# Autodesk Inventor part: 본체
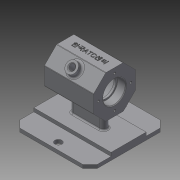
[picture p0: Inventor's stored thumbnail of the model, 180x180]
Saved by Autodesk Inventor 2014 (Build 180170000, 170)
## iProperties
Created: 2018-06
Part Number: 본체
Material: Generic
Document SubType Name: Modeling
Designer: geosung1
Density: 1 g/cm^3
Appearance: Default
Author: geosung1
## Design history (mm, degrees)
sketch "스케치1" dims "d0" = 60
  geometry: L1 (12.426, 30)-(30, 12.426); L2 (30, 12.426)-(30, -12.426); L3 (30, -12.426)-(12.426, -30); L4 (12.426, -30)-(-12.426, -30); L5 (-12.426, -30)-(-30, -12.426); L6 (-30, -12.426)-(-30, 12.426); L7 (-30, 12.426)-(-12.426, 30); L8 (-12.426, 30)-(12.426, 30); 4 further points
  constraints: 16 end point, 2 coincident, 2 vertical alignment, 1 midpoint, 19 other
extrude "돌출1" new body sketch "스케치1" stored distance "d1" = 70; taper "d2" = 0 deg
sketch "스케치2"
  geometry: L1 (-44.066, 0)-(44.066, 0); L2 (-35, -30)-(-35, 30) reference; L3 (-35, 30)-(35, 30) reference; L4 (35, 30)-(35, -30) reference; L5 (35, -30)-(-35, -30) reference; L6 (-35, 16)-(-23, 16); L7 (-23, 16)-(-23, 14); L8 (-23, 14)-(-20, 14); L9 (-20, 14)-(-20, 25); L10 (-20, 25)-(20, 25); L11 (20, 25)-(20, 14); L12 (20, 14)-(23, 14); L13 (23, 14)-(23, 16); L14 (23, 16)-(35, 16); L15 (-35, -30)-(-35, 30) reference; L16 (-35, 30)-(35, 30) reference; L17 (35, 30)-(35, -30) reference; L18 (35, -30)-(-35, -30) reference; L19 (-35, 16)-(-35, 0); L20 (35, 16)-(35, 0); L21 (-35, 0)-(35, 0); 2 further points
  constraints: 26 end point, 7 parallel, 4 equal length, 3 midpoint, 2 perpendicular, 2 point on line, 1 coincident, 1 collinear, 1 horizontal
  dimensions: "d3" = 28 diameter of L12 L1; "d4" = 32 diameter of L14 L1; "d5" = 50 diameter of L10 L1; "d6" = 12 distance of L6.start L6.end; "d7" = 3 distance of L7.end L8.end
revolve "회전1" sketch "스케치2" stored, may be unused: angle "d8" = 90 deg
sketch "스케치3" dims "d9" = 46
  geometry: C1 r 16 at (0, 0) reference; 2 further points
  constraints: 2 vertical alignment, 1 coincident, 2 other
hole "구멍1" sketch "스케치3" at (0, 23) diameter "d10" = 3.242; stored, may be unused: countersink angle "d14" = 90 deg, drill point angle "d16" = 118 deg; dims "d11" = 6, "d12" = 4, "d13" = 2, "d15" = 10
node "작업 평면1"
sketch "스케치4"
  geometry: L1 (-55, 55)-(55, 55); L2 (55, 55)-(55, -55); L3 (55, -55)-(-55, -55); L4 (-55, -55)-(-55, 55); L5 (-55, 55)-(55, -55); L6 (55, 55)-(-55, -55); 1 further point
  constraints: 12 end point, 2 midpoint, 2 parallel, 1 horizontal, 1 perpendicular
  dimensions: "d21" = 110 distance of L2.end L3.end; "d22" = 110 distance of L3.end L1.start
extrude "돌출2" join sketch "스케치4" distance "d23" = 5; taper "d24" = 0 deg
sketch "스케치5"
  geometry: L1 (-55, -55)-(55, -55) reference; L2 (55, 55)-(-55, 55) reference; L3 (-55, 55)-(-55, -55) reference; L4 (55, -25)-(-55, -25); L5 (-55, -25)-(-55, 25); L6 (-55, 25)-(55, 25); L7 (55, 25)-(55, -25); L8 (55, -25)-(-55, 25); L9 (-55, -25)-(55, 25); 1 further point
  constraints: 12 end point, 2 midpoint, 2 parallel, 1 horizontal, 1 perpendicular, 1 point on line
  dimensions: "d25" = 30 distance between parallel lines of L6 L2; "d26" = 30 distance between parallel lines of L1 L4 (derived)
extrude "돌출3" join sketch "스케치5" distance "d27" = 5; taper "d28" = 0 deg
sketch "스케치6"
  geometry: L1 (-55, -25)-(55, -25) reference; L2 (19, 0)-(-19, 0); L3 (19, -5)-(-19, -5); L4 (-19, 5)-(19, 5); A1 r 5 centre (19, 0) between (19, -5) and (19, 5); A2 r 5 centre (-19, 0) between (-19, 5) and (-19, -5); 2 further points
  constraints: 8 end point, 4 point on circle, 4 tangent, 2 centre point, 2 parallel, 1 coincident, 1 midpoint
  dimensions: "d29" = 5 radius of A1; "d30" = 38 distance of L2.start L2.end
extrude "돌출4" join sketch "스케치6" stored distance "d31" = 5; taper "d32" = 0 deg
sketch "스케치7"
  geometry: L1 (-55, -55)-(55, -55) reference; L2 (55, -55)-(55, -25) reference; C1 r 5 at (0, -45); 1 further point
  constraints: 1 centre point
  dimensions: "d33" = 55 distance from line of L2 C1.centre; "d34" = 10 distance from line of L1 C1.centre; "d35" = 10 diameter of C1
extrude "돌출5" cut sketch "스케치7" stored distance "d36" = 5; taper "d37" = 0 deg
sketch "스케치8"
  geometry: L1 (0, 0)-(0, 56.034); L2 (0, 0)-(26.163, 26.163); L3 (30, 12.426)-(12.426, 30) reference
  constraints: 4 end point, 1 vertical
  dimensions: "d38" = 45 deg angle of L1 L2; "d39" = 7 distance from line of L3 L2.end
node "작업 평면2"
sketch "스케치9"
  geometry: C1 r 8 at (0, 0); 1 further point
  constraints: 1 centre point, 1 coincident
  dimensions: "d40" = 16 diameter of C1
extrude "돌출6" join sketch "스케치9" stored distance "d41" = 5; taper "d42" = 0 deg
sketch "스케치10"
  geometry: C1 r 8 at (0, 0) reference; C2 r 4 at (0, 0)
  constraints: 1 centre point, 1 coincident
  dimensions: "d43" = 8 diameter of C2
extrude "돌출7" cut sketch "스케치10" distance "d44" = 30; taper "d45" = 0 deg
node "작업 평면3"
sketch "스케치11"
  geometry: L1 (-35, -30)-(35, -30) reference; L2 (35, 12.426)-(35, -12.426) reference; 2 further points
  constraints: 1 other
  dimensions: "d47" = 35 distance from line of L2 point (0, 0); "d48" = 30 distance from line of L1 point (0, 0)
feature "엠보싱1" sketch "스케치11" dims "d3" = 28, "d4" = 32, "d5" = 50, "d6" = 12, "d7" = 3, "d49" = 0.5, "d50" = 0
chamfer "모따기1" distance "d51" = 1; stored, may be unused: second distance "d52" = 2, angle "d53" = 45 deg
chamfer "모따기2" distance "d54" = 1; stored, may be unused: second distance "d55" = 2, angle "d56" = 45 deg
fillet "모깎기1" dims "d57" = 3
fillet "모깎기2" dims "d58" = 3
fillet "모깎기3" dims "d59" = 1
chamfer "모따기3" distance "d60" = 10; stored, may be unused: second distance "d61" = 2, angle "d62" = 45 deg
fillet "모깎기4" dims "d63" = 2
fillet "모깎기5" dims "d64" = 0.3
node "솔리드1"
pattern_circular "원형 패턴1" dims angle "d18" = 360 deg
mirror "대칭1"
mirror "대칭2"
node "절단 모서리 투영1"
node "절단 모서리 투영2"
other parameters: "d20" = -62, "d46" = 40.25
